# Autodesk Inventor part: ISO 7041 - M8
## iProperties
Comments: To add or edit properties for Autodesk Inventor files, use iProperties.
Created: 2004-03
Part Number: ISO 7041 - M8
Vendor: Autodesk Inc.
Document SubType Name: Modeling
Designer: rak
Material: Default
Description: Hex Nut with Torque Part
Standard: ISO 7041
Size Designation: M8
Alert: To add or edit properties for Autodesk Inventor files, use iProperties.
Control State: 0
Master: False
Checked Out: False
Shininess: 64.0
Length Units: 11269
Angle Units: 11279
Time Units: 11290
Mass Units: 11283
Length Display Precision: 3
Angle Display Precision: 2
Compacted: True
EGR: 1
Density: 0.0
Volumn: 0.0
Area: 0.0
PropertySet Name: Model Information
Author: rak
Revision Number: 8
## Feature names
1. Body [Extrusion]
2. Ring [Extrusion]
3. Chamfer1 [Revolution]
4. Thread [Hole]
5. Chamfer2
6. Chamfer3
